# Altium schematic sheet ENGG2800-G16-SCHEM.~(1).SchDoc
size A4
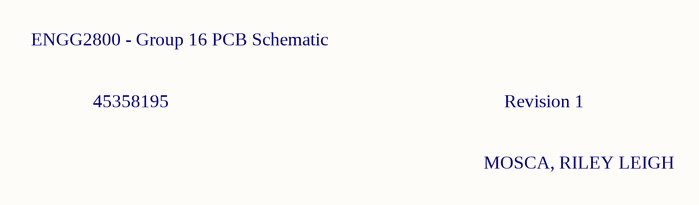
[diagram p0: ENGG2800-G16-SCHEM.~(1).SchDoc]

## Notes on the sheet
- ENGG2800 - Group 16 PCB Schematic
- 45358195
- Revision 1
- MOSCA, RILEY LEIGH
